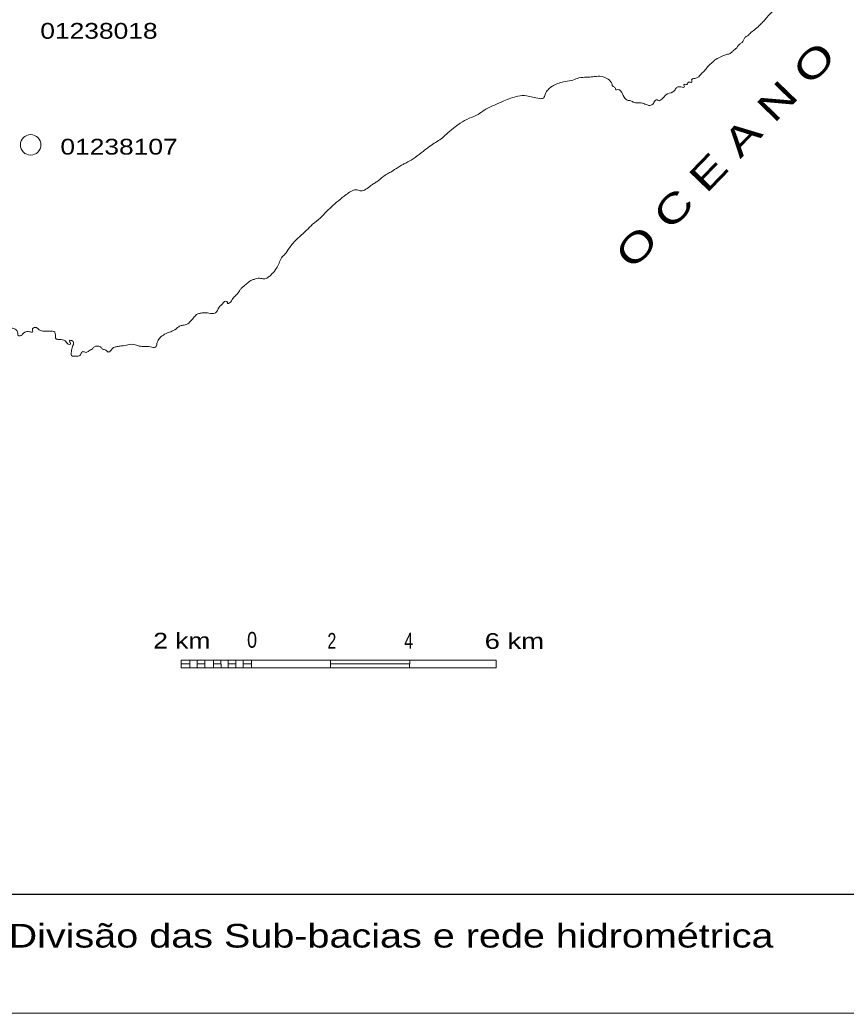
# Model space of a CAD drawing. Extents: x 854879 to 917879, y 8541948 to 8631048.
# Drawn here: x 879557 to 900512, y 8541948 to 8567127 of the extents above; entities that cross this region are included whole.
import ezdxf
from ezdxf.enums import TextEntityAlignment as Align

# ---------------------------------------------------------------- set-up
doc = ezdxf.new("R2010")
doc.units = 0
doc.header["$LTSCALE"] = 160
for name, color, linetype, lineweight in [('1', 7, 'Continuous', 13), ('18', 7, 'Continuous', 13), ('3', 7, 'Continuous', 13), ('36', 7, 'Continuous', 13), ('40', 7, 'Continuous', 13), ('44', 7, 'Continuous', 13), ('53', 7, 'Continuous', 13)]:
    doc.layers.add(name, color=color, linetype=linetype, lineweight=lineweight)

msp = doc.modelspace()

# ---------------------------------------------------------------- linework, layer by layer
at = {"layer": '1'}
msp.add_lwpolyline([(916445.6, 8586427.1), (916445.6, 8544954.2), (858846.4, 8544954.2), (858846.4, 8599885.6)], dxfattribs=at)
msp.add_circle((879830.7, 8563958.2), 260.2, dxfattribs=at)
at = {"layer": '18'}
for points in [[(905444.1, 8574465.6), (905336.9, 8574299.7), (905311.9, 8574201.4), (905284.7, 8574110.8), (905247.5, 8574079.4), (905189, 8574082.1), (905101.9, 8574019.8), (905038.7, 8573976.8), (904957.8, 8573937.2), (904876.3, 8573884.8), (904837.6, 8573876.4), (904749.4, 8573898.4), (904632.1, 8573845.1), (904112.8, 8573593.6), (904080.4, 8573554.3), (903999.8, 8573522.3), (903907.3, 8573452.7), (903784, 8573323.2), (903625.1, 8573197.9), (903530.5, 8573084.9), (903454.5, 8572930.3), (903209.3, 8572650.9), (902748.6, 8572123.8), (902622, 8571979.2), (902451, 8571813.7), (902293.7, 8571667.9), (902180.1, 8571527.8), (902102.6, 8571398.7), (902002.9, 8571283.5), (901951.8, 8571227.2), (901902.2, 8571147.9), (901834.2, 8571056.6), (901712.6, 8570911.8), (901623.8, 8570811.3), (901543.5, 8570677.3), (901389.1, 8570482.9), (901221.9, 8570289.2), (901083.8, 8570117), (900970.9, 8569938.6), (900875.4, 8569805.3), (900753.8, 8569657.9), (900585.2, 8569433.6), (900467.5, 8569263), (900363.3, 8569160.7), (900257.6, 8569081.4), (900165.9, 8568976), (900095.5, 8568887.5), (900016, 8568768.7), (899958.5, 8568684.7), (899878.9, 8568563.3), (899790.3, 8568468), (899727.7, 8568384.2), (899666.8, 8568282.4), (899539.5, 8568122.5), (899420.9, 8568041.3), (899213.7, 8567864.7), (899115.2, 8567774.8), (898954.8, 8567672.6), (898836.9, 8567550.5), (898761.4, 8567462.2), (898506.5, 8567193.4), (898423, 8567097.8), (898337.3, 8567009.9), (898217.3, 8566898.1), (898098.1, 8566804.2), (898007.7, 8566724.2), (897941.8, 8566678.8), (897872.1, 8566551.9), (897814.2, 8566513.8), (897708.9, 8566388.6), (897661.6, 8566357.6), (897602.7, 8566299.1), (897537.2, 8566261.3), (897470.2, 8566246.6), (897332.3, 8566189.2), (897209.5, 8566126), (897087.2, 8566019.4), (896996.8, 8565939.4), (896920.7, 8565838.4), (896845.8, 8565765.3), (896778.4, 8565686.8), (896702.8, 8565652.1), (896638.4, 8565637.2), (896596.7, 8565618.7), (896595.1, 8565585.6), (896601.8, 8565564.9), (896582.7, 8565537.7), (896555, 8565544.1), (896514.3, 8565548.5), (896486.6, 8565501.4), (896447.6, 8565485.3)], [(896447.6, 8565485.3), (896401.9, 8565490), (896393.4, 8565470), (896415, 8565440.9), (896396.1, 8565418.8), (896355.3, 8565420.7), (896212, 8565409.5), (896162.8, 8565337.8), (896117.6, 8565299.1), (895940.8, 8565228.2), (895889.6, 8565169.3), (895836.1, 8565115.7), (895745.2, 8565079.1), (895715.7, 8565103.4), (895671.2, 8565079.9), (895608.3, 8564988.5), (895556, 8564960.3), (895467.2, 8564972), (895349.3, 8565013.2), (895209.7, 8565027.3), (895133.5, 8565033.3), (895051.2, 8565075.4), (894960.2, 8565092.3), (894882.1, 8565167.4), (894792.5, 8565324.5), (894722.7, 8565358.3), (894668.9, 8565353.2), (894660.1, 8565384.2), (894641.1, 8565413.1), (894582.3, 8565464.3), (894576.1, 8565495.2), (894474.9, 8565622.3), (894266.7, 8565698.2), (894090.1, 8565683.4), (893926.5, 8565675.6), (893736.7, 8565653.8), (893583.8, 8565602.2), (893385.5, 8565560.3), (893087.7, 8565464.4), (892992.8, 8565397.4), (892914.7, 8565309.2), (892875.6, 8565237), (892833, 8565144.6), (892735.5, 8565131.3), (892404.7, 8565202.6), (892190, 8565192.1), (891832.4, 8565070.9), (891608.4, 8564971.6), (891347.6, 8564848.5), (891176.3, 8564731.4), (890952.4, 8564632.1), (890724.7, 8564507.4), (890598, 8564416.3), (890412.4, 8564264.2), (890271.3, 8564138.1), (889997.3, 8563951.8), (889831, 8563829.5), (889427.3, 8563542.1), (889314.9, 8563483.5), (889239, 8563441.1), (889131.4, 8563377.2), (888989.4, 8563284.3), (888877, 8563225.7), (888760.9, 8563144.3), (888609.9, 8563023.8), (888520.7, 8562969.2), (888428.4, 8562904.7), (888294.1, 8562813.9), (888188.6, 8562793.3), (888080.1, 8562818.7), (887950.7, 8562778.8), (887834.8, 8562700), (887636.1, 8562540.8), (887292.3, 8562225.1), (887174.4, 8562103.1), (886980.8, 8561943.7), (886828.5, 8561795.1), (886647.3, 8561630.1), (886481.3, 8561461.8), (886391.8, 8561346), (886279.7, 8561185.4), (886191.3, 8561095.1), (886131.2, 8560955.1), (886066.8, 8560830.5), (885958.4, 8560695.3), (885881.2, 8560624.9), (885799.7, 8560572.5), (885735.4, 8560562.7), (885697.4, 8560567.1), (885634.2, 8560580.2), (885497.6, 8560548.2)], [(885497.6, 8560548.2), (885456.3, 8560537.4), (885414.6, 8560518.9), (885306, 8560432.1), (885226.5, 8560369.4), (885170.6, 8560318.5), (885126.9, 8560256.7), (885091.3, 8560204.8), (885037.6, 8560146.1), (884959.6, 8560060.4), (884875.6, 8559954.6), (884823.8, 8559936.6), (884822.4, 8559962.2), (884770.3, 8559992.7), (884698.6, 8559932.2), (884610.2, 8559841.9), (884514.2, 8559698.4), (884345.7, 8559693.4), (884231.4, 8559703.8), (884131.3, 8559690.6), (884056.3, 8559668.6), (883981.6, 8559598), (883898.1, 8559502.4), (883820.5, 8559424.4), (883724.4, 8559388), (883624, 8559367.2), (883558.2, 8559324.3), (883408.5, 8559231.7), (883299.5, 8559190.9), (883163.3, 8559115.5), (883080.3, 8559030.1), (883034.3, 8558920), (882994.3, 8558827.5), (882867.3, 8558838.4), (882709.6, 8558848.3), (882585.2, 8558859.1), (882449.3, 8558898.6), (882198.1, 8558871.9), (882097.9, 8558856.1), (882002.8, 8558840.1), (881917, 8558805.8), (881863, 8558742), (881800.2, 8558706.6), (881738.5, 8558752.8), (881655.8, 8558782.2), (881602.1, 8558835.6), (881516.4, 8558857.4), (881449.2, 8558837.6), (881396, 8558791.6), (881301.3, 8558729.7), (881236.1, 8558697), (881152.8, 8558716.1), (881104, 8558654.6), (881079.6, 8558622.6), (880976.6, 8558601.8), (880870.2, 8558616.9), (880864.7, 8558719.2), (880890.9, 8558842.9), (880916.6, 8558956.5), (880852.5, 8559002.8), (880821.7, 8558999.2), (880815.3, 8558971.4), (880832, 8558947.7), (880840.2, 8558903.9), (880781.8, 8558909.2), (880703.9, 8558989.3), (880557.6, 8559024.1), (880471.9, 8559045.9), (880458, 8559130.7), (880443.8, 8559207.9), (880284.4, 8559235.7), (880141.7, 8559239.7), (880043.8, 8559272.3), (879980, 8559326.2), (879921.3, 8559326.4), (879879, 8559292.6), (879880, 8559259.4), (879885.9, 8559223.4), (879801.7, 8559222.2), (879681.3, 8559209.9), (879660.2, 8559195.6), (879627.9, 8559158.8), (879567.2, 8559115.7), (879504.2, 8559131.4), (879503.2, 8559164.6), (879476.7, 8559252.5), (879397.5, 8559304.6), (879275.1, 8559305.2), (879008.8, 8559228.2), (878863.5, 8559229.8), (878737.4, 8559261.1)]]:
    msp.add_spline(points, degree=3, dxfattribs=at)
at = {"layer": '3'}
for points in [[(905444.1, 8574465.6), (905336.9, 8574299.7), (905311.9, 8574201.4), (905284.7, 8574110.8), (905247.5, 8574079.4), (905189, 8574082.1), (905101.9, 8574019.8), (905038.7, 8573976.8), (904957.8, 8573937.2), (904876.3, 8573884.8), (904837.6, 8573876.4), (904749.4, 8573898.4), (904632.1, 8573845.1), (904112.8, 8573593.6), (904080.4, 8573554.3), (903999.8, 8573522.3), (903907.3, 8573452.7), (903784, 8573323.2), (903625.1, 8573197.9), (903530.5, 8573084.9), (903454.5, 8572930.3), (903209.3, 8572650.9), (902748.6, 8572123.8), (902622, 8571979.2), (902451, 8571813.7), (902293.7, 8571667.9), (902180.1, 8571527.8), (902102.6, 8571398.7), (902002.9, 8571283.5), (901951.8, 8571227.2), (901902.2, 8571147.9), (901834.2, 8571056.6), (901712.6, 8570911.8), (901623.8, 8570811.3), (901543.5, 8570677.3), (901389.1, 8570482.9), (901221.9, 8570289.2), (901083.8, 8570117), (900970.9, 8569938.6), (900875.4, 8569805.3), (900753.8, 8569657.9), (900585.2, 8569433.6), (900467.5, 8569263), (900363.3, 8569160.7), (900257.6, 8569081.4), (900165.9, 8568976), (900095.5, 8568887.5), (900016, 8568768.7), (899958.5, 8568684.7), (899878.9, 8568563.3), (899790.3, 8568468), (899727.7, 8568384.2), (899666.8, 8568282.4), (899539.5, 8568122.5), (899420.9, 8568041.3), (899213.7, 8567864.7), (899115.2, 8567774.8), (898954.8, 8567672.6), (898836.9, 8567550.5), (898761.4, 8567462.2), (898506.5, 8567193.4), (898423, 8567097.8), (898337.3, 8567009.9), (898217.3, 8566898.1), (898098.1, 8566804.2), (898007.7, 8566724.2), (897941.8, 8566678.8), (897872.1, 8566551.9), (897814.2, 8566513.8), (897708.9, 8566388.6), (897661.6, 8566357.6), (897602.7, 8566299.1), (897537.2, 8566261.3), (897470.2, 8566246.6), (897332.3, 8566189.2), (897209.5, 8566126), (897087.2, 8566019.4), (896996.8, 8565939.4), (896920.7, 8565838.4), (896845.8, 8565765.3), (896778.4, 8565686.8), (896702.8, 8565652.1), (896638.4, 8565637.2), (896596.7, 8565618.7), (896595.1, 8565585.6), (896601.8, 8565564.9), (896582.7, 8565537.7), (896555, 8565544.1), (896514.3, 8565548.5), (896486.6, 8565501.4), (896447.6, 8565485.3)], [(896447.6, 8565485.3), (896401.9, 8565490), (896393.4, 8565470), (896415, 8565440.9), (896396.1, 8565418.8), (896355.3, 8565420.7), (896212, 8565409.5), (896162.8, 8565337.8), (896117.6, 8565299.1), (895940.8, 8565228.2), (895889.6, 8565169.3), (895836.1, 8565115.7), (895745.2, 8565079.1), (895715.7, 8565103.4), (895671.2, 8565079.9), (895608.3, 8564988.5), (895556, 8564960.3), (895467.2, 8564972), (895349.3, 8565013.2), (895209.7, 8565027.3), (895133.5, 8565033.3), (895051.2, 8565075.4), (894960.2, 8565092.3), (894882.1, 8565167.4), (894792.5, 8565324.5), (894722.7, 8565358.3), (894668.9, 8565353.2), (894660.1, 8565384.2), (894641.1, 8565413.1), (894582.3, 8565464.3), (894576.1, 8565495.2), (894474.9, 8565622.3), (894266.7, 8565698.2), (894090.1, 8565683.4), (893926.5, 8565675.6), (893736.7, 8565653.8), (893583.8, 8565602.2), (893385.5, 8565560.3), (893087.7, 8565464.4), (892992.8, 8565397.4), (892914.7, 8565309.2), (892875.6, 8565237), (892833, 8565144.6), (892735.5, 8565131.3), (892404.7, 8565202.6), (892190, 8565192.1), (891832.4, 8565070.9), (891608.4, 8564971.6), (891347.6, 8564848.5), (891176.3, 8564731.4), (890952.4, 8564632.1), (890724.7, 8564507.4), (890598, 8564416.3), (890412.4, 8564264.2), (890271.3, 8564138.1), (889997.3, 8563951.8), (889831, 8563829.5), (889427.3, 8563542.1), (889314.9, 8563483.5), (889239, 8563441.1), (889131.4, 8563377.2), (888989.4, 8563284.3), (888877, 8563225.7), (888760.9, 8563144.3), (888609.9, 8563023.8), (888520.7, 8562969.2), (888428.4, 8562904.7), (888294.1, 8562813.9), (888188.6, 8562793.3), (888080.1, 8562818.7), (887950.7, 8562778.8), (887834.8, 8562700), (887636.1, 8562540.8), (887292.3, 8562225.1), (887174.4, 8562103.1), (886980.8, 8561943.7), (886828.5, 8561795.1), (886647.3, 8561630.1), (886481.3, 8561461.8), (886391.8, 8561346), (886279.7, 8561185.4), (886191.3, 8561095.1), (886131.2, 8560955.1), (886066.8, 8560830.5), (885958.4, 8560695.3), (885881.2, 8560624.9), (885799.7, 8560572.5), (885735.4, 8560562.7), (885697.4, 8560567.1), (885634.2, 8560580.2), (885497.6, 8560548.2)], [(885497.6, 8560548.2), (885456.3, 8560537.4), (885414.6, 8560518.9), (885306, 8560432.1), (885226.5, 8560369.4), (885170.6, 8560318.5), (885126.9, 8560256.7), (885091.3, 8560204.8), (885037.6, 8560146.1), (884959.6, 8560060.4), (884875.6, 8559954.6), (884823.8, 8559936.6), (884822.4, 8559962.2), (884770.3, 8559992.7), (884698.6, 8559932.2), (884610.2, 8559841.9), (884514.2, 8559698.4), (884345.7, 8559693.4), (884231.4, 8559703.8), (884131.3, 8559690.6), (884056.3, 8559668.6), (883981.6, 8559598), (883898.1, 8559502.4), (883820.5, 8559424.4), (883724.4, 8559388), (883624, 8559367.2), (883558.2, 8559324.3), (883408.5, 8559231.7), (883299.5, 8559190.9), (883163.3, 8559115.5), (883080.3, 8559030.1), (883034.3, 8558920), (882994.3, 8558827.5), (882867.3, 8558838.4), (882709.6, 8558848.3), (882585.2, 8558859.1), (882449.3, 8558898.6), (882198.1, 8558871.9), (882097.9, 8558856.1), (882002.8, 8558840.1), (881917, 8558805.8), (881863, 8558742), (881800.2, 8558706.6), (881738.5, 8558752.8), (881655.8, 8558782.2), (881602.1, 8558835.6), (881516.4, 8558857.4), (881449.2, 8558837.6), (881396, 8558791.6), (881301.3, 8558729.7), (881236.1, 8558697), (881152.8, 8558716.1), (881104, 8558654.6), (881079.6, 8558622.6), (880976.6, 8558601.8), (880870.2, 8558616.9), (880864.7, 8558719.2), (880890.9, 8558842.9), (880916.6, 8558956.5), (880852.5, 8559002.8), (880821.7, 8558999.2), (880815.3, 8558971.4), (880832, 8558947.7), (880840.2, 8558903.9), (880781.8, 8558909.2), (880703.9, 8558989.3), (880557.6, 8559024.1), (880471.9, 8559045.9), (880458, 8559130.7), (880443.8, 8559207.9), (880284.4, 8559235.7), (880141.7, 8559239.7), (880043.8, 8559272.3), (879980, 8559326.2), (879921.3, 8559326.4), (879879, 8559292.6), (879880, 8559259.4), (879885.9, 8559223.4), (879801.7, 8559222.2), (879681.3, 8559209.9), (879660.2, 8559195.6), (879627.9, 8559158.8), (879567.2, 8559115.7), (879504.2, 8559131.4), (879503.2, 8559164.6), (879476.7, 8559252.5), (879397.5, 8559304.6), (879275.1, 8559305.2), (879008.8, 8559228.2), (878863.5, 8559229.8), (878737.4, 8559261.1)]]:
    msp.add_spline(points, degree=3, dxfattribs=at)
at = {"layer": '36'}
msp.add_lwpolyline([(854878.6, 8541948.4), (917878.6, 8541948.4), (917878.6, 8631048.4), (854878.6, 8631048.4)], close=True, dxfattribs=at)
at = {"layer": '36', "lineweight": 25}
msp.add_lwpolyline([(858846.4, 8628560.7), (916445.6, 8628560.7), (916445.6, 8544954.2), (858846.4, 8544954.2)], close=True, dxfattribs=at)
at = {"layer": '40'}
for p, q in [((883651.3, 8550898.4), (883651.3, 8550702.4)), ((883864.8, 8550898.4), (883865.3, 8550702.4)), ((884053.5, 8550898.4), (884052.8, 8550702.4)), ((884249.6, 8550898.4), (884250.5, 8550702.4)), ((884468.9, 8550898.4), (884468.6, 8550702.4)), ((884657.5, 8550898.4), (884658.2, 8550702.4)), ((884840.9, 8550898.4), (884841.6, 8550702.4)), ((885037.3, 8550898.4), (885037.3, 8550702.4)), ((885220.8, 8550898.4), (885219.8, 8550702.4)), ((885432.1, 8550898.4), (885431.4, 8550702.4)), ((887433.4, 8550898.4), (887432.4, 8550702.4)), ((889444.4, 8550898.4), (889440.9, 8550702.4)), ((883651.3, 8550800.4), (883865, 8550800.4)), ((884053.1, 8550800.4), (884250.1, 8550800.4)), ((884468.8, 8550800.4), (884657.8, 8550800.4)), ((884841.3, 8550800.4), (885037.3, 8550800.4)), ((885220.3, 8550800.4), (885431.8, 8550800.4)), ((887432.9, 8550800.4), (889442.7, 8550800.4))]:
    msp.add_line(p, q, dxfattribs=at)
msp.add_lwpolyline([(883651.3, 8550898.4), (891633.8, 8550898.4), (891633.8, 8550702.4), (883651.3, 8550702.4)], close=True, dxfattribs=at)
at = {"layer": '44'}
msp.add_lwpolyline([(858846.4, 8628560.7), (916445.6, 8628560.7), (916445.6, 8544954.2), (858846.4, 8544954.2)], close=True, dxfattribs=at)

# ---------------------------------------------------------------- texts
at = {"layer": '1', "width": 1.25}
for s, p in [('01238018', (881562.4, 8566648.3)), ('01238107', (882072.2, 8563711.3))]:
    msp.add_text(s, height=400, dxfattribs=at).set_placement(p, align=Align.CENTER)
at = {"layer": '3', "width": 1.4}
msp.add_text('O C E A N O', height=700, rotation=45.995, dxfattribs=at).set_placement((895093.8, 8560764.6))
at = {"layer": '40'}
for s, width, p in [('2 km', 1.25, (883663.5, 8551190.7)), ('0', 0.85, (885445.9, 8551210.8)), ('2', 0.75, (887469.7, 8551185.8)), ('4', 0.75, (889418.4, 8551190.7)), ('6 km', 1.3, (892098.4, 8551180.9))]:
    msp.add_text(s, height=400, dxfattribs=dict(at, width=width)).set_placement(p, align=Align.CENTER)
at = {"layer": '53', "width": 1.25}
msp.add_text('Figura 4.1: Divisão das Sub-bacias e rede hidrométrica', height=600, dxfattribs=at).set_placement((886433.6, 8543610.7), align=Align.CENTER)

doc.saveas('drawing.dxf')
